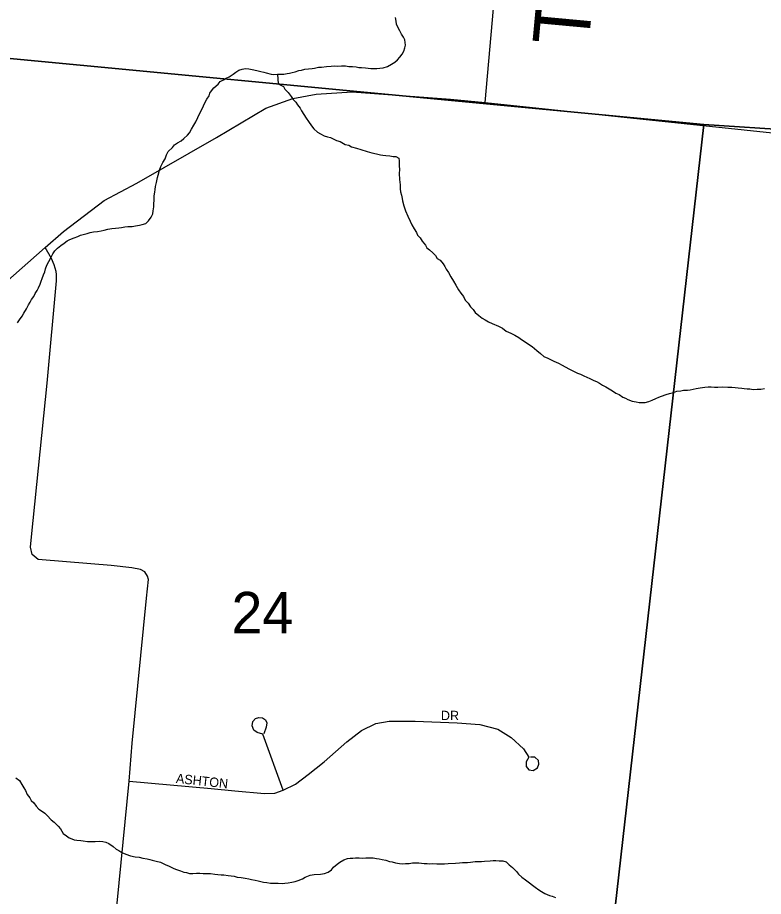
# Model space of a CAD drawing. Extents: x 0 to 1064, y 0 to 440.
# Drawn here: x 282.84 to 294.9, y 236.99 to 251.21 of the extents above; entities that cross this region are included whole.
import ezdxf

# ---------------------------------------------------------------- set-up
doc = ezdxf.new("R2010")
doc.units = 0
for name, color, linetype in [('GM_X_County_Road', 7, 'Continuous'), ('GM_X_Minor_River', 7, 'Continuous'), ('GM_X_Section', 7, 'Continuous'), ('GM_X_Section_Text', 7, 'Continuous'), ('GM_X_Township_Road', 7, 'Continuous'), ('GM_X_Township_Road_Text', 7, 'Continuous'), ('GM_X_Township_Subdivision', 7, 'Continuous'), ('GM_X_Township_Subdivision_Text', 7, 'Continuous')]:
    doc.layers.add(name, color=color, linetype=linetype)

msp = doc.modelspace()

# ---------------------------------------------------------------- linework, layer by layer
at = {"layer": 'GM_X_County_Road'}
msp.add_lwpolyline([(282.12, 246.458), (283.289, 247.487), (283.585, 247.745), (284.245, 248.251), (284.769, 248.528), (286.06, 249.268), (286.855, 249.742), (287.293, 249.898), (287.673, 249.968), (288.256, 250.004), (289.845, 249.886), (290.404, 249.835), (296.737, 249.166)], dxfattribs=at)
at = {"layer": 'GM_X_Minor_River'}
for points in [[(287.39, 250.352), (287.433, 250.357), (287.488, 250.374), (287.549, 250.378), (287.604, 250.382), (287.647, 250.387), (287.708, 250.403), (287.757, 250.408), (287.837, 250.417), (287.916, 250.421), (287.971, 250.425), (288.019, 250.424), (288.081, 250.428), (288.147, 250.426), (288.202, 250.418), (288.257, 250.417), (288.317, 250.409), (288.36, 250.401), (288.402, 250.4), (288.469, 250.392), (288.512, 250.391), (288.554, 250.383), (288.603, 250.382), (288.651, 250.386), (288.7, 250.391), (288.755, 250.395), (288.823, 250.417), (288.891, 250.452), (288.941, 250.487), (288.985, 250.522), (289.023, 250.569), (289.061, 250.617), (289.087, 250.664), (289.107, 250.718), (289.114, 250.761), (289.11, 250.803), (289.105, 250.846), (289.082, 250.889), (289.053, 250.939), (289.025, 250.994), (288.99, 251.05), (288.973, 251.099), (288.963, 251.148), (288.953, 251.209)], [(283.263, 247.048), (283.283, 247.096), (283.296, 247.144), (283.317, 247.205), (283.349, 247.264), (283.382, 247.324), (283.414, 247.384), (283.446, 247.437), (283.49, 247.479), (283.54, 247.52), (283.596, 247.56), (283.646, 247.595), (283.69, 247.618), (283.757, 247.646), (283.819, 247.669), (283.862, 247.686), (283.905, 247.697), (283.967, 247.713), (284.016, 247.73), (284.071, 247.74), (284.138, 247.75), (284.193, 247.761), (284.243, 247.771), (284.304, 247.787), (284.365, 247.798), (284.426, 247.802), (284.481, 247.806), (284.524, 247.811), (284.579, 247.822), (284.628, 247.826), (284.695, 247.83), (284.75, 247.841), (284.817, 247.851), (284.86, 247.861), (284.916, 247.878), (284.96, 247.919), (285.004, 247.978), (285.03, 248.032), (285.038, 248.081), (285.046, 248.147), (285.048, 248.202), (285.05, 248.25), (285.052, 248.323), (285.06, 248.384), (285.068, 248.426), (285.075, 248.474), (285.09, 248.541), (285.105, 248.619), (285.118, 248.661), (285.139, 248.739), (285.159, 248.8), (285.192, 248.865), (285.23, 248.925), (285.251, 248.985), (285.277, 249.039), (285.346, 249.104), (285.378, 249.151), (285.427, 249.18), (285.489, 249.215), (285.533, 249.25), (285.59, 249.303), (285.622, 249.344), (285.654, 249.404), (285.693, 249.469), (285.725, 249.523), (285.757, 249.589), (285.797, 249.673), (285.829, 249.732), (285.849, 249.78), (285.869, 249.828), (285.901, 249.888), (285.94, 249.942), (285.953, 249.984), (285.979, 250.025), (286.017, 250.073), (286.086, 250.131), (286.118, 250.173), (286.173, 250.202), (286.217, 250.225), (286.266, 250.247), (286.329, 250.294), (286.372, 250.323), (286.422, 250.358), (286.477, 250.374), (286.526, 250.385), (286.581, 250.377), (286.636, 250.37), (286.714, 250.349), (286.774, 250.335), (286.823, 250.327), (286.865, 250.314), (286.944, 250.293), (286.986, 250.286), (287.047, 250.29), (287.108, 250.294), (287.151, 250.293), (287.2, 250.304), (287.242, 250.308), (287.285, 250.319), (287.334, 250.33), (287.39, 250.352)], [(287.047, 250.29), (287.059, 250.138), (287.144, 250.093), (287.167, 250.049), (287.22, 249.993), (287.267, 249.931), (287.301, 249.881), (287.343, 249.838), (287.372, 249.794), (287.413, 249.744), (287.436, 249.701), (287.47, 249.639), (287.511, 249.583), (287.546, 249.528), (287.598, 249.459), (287.633, 249.41), (287.692, 249.353), (287.74, 249.327), (287.8, 249.295), (287.854, 249.281), (287.902, 249.268), (287.944, 249.248), (287.998, 249.222), (288.058, 249.202), (288.142, 249.157), (288.197, 249.143), (288.244, 249.117), (288.323, 249.097), (288.395, 249.076), (288.498, 249.043), (288.57, 249.022), (288.649, 249.002), (288.709, 248.988), (288.751, 248.98), (288.8, 248.979), (288.861, 248.971), (288.915, 248.963), (288.958, 248.962), (289.006, 248.936), (289.016, 248.893), (289.015, 248.851), (289.014, 248.808), (289.018, 248.753), (289.016, 248.687), (289.019, 248.589), (289.028, 248.504), (289.032, 248.437), (289.036, 248.389), (289.053, 248.333), (289.063, 248.284), (289.068, 248.242), (289.09, 248.162), (289.118, 248.082), (289.151, 247.996), (289.191, 247.916), (289.22, 247.854), (289.254, 247.793), (289.295, 247.731), (289.312, 247.688), (289.353, 247.644), (289.388, 247.594), (289.44, 247.526), (289.463, 247.483), (289.505, 247.451), (289.558, 247.401), (289.599, 247.357), (289.628, 247.313), (289.676, 247.282), (289.723, 247.226), (289.752, 247.182), (289.775, 247.139), (289.809, 247.083), (289.85, 247.015), (289.89, 246.947), (289.931, 246.879), (289.971, 246.805), (290.012, 246.749), (290.053, 246.699), (290.081, 246.638), (290.128, 246.587), (290.169, 246.532), (290.21, 246.488), (290.245, 246.438), (290.304, 246.388), (290.357, 246.344), (290.405, 246.318), (290.459, 246.286), (290.519, 246.26), (290.621, 246.214), (290.687, 246.182), (290.746, 246.137), (290.818, 246.105), (290.884, 246.072), (290.95, 246.034), (290.992, 246.002), (291.051, 245.964), (291.105, 245.926), (291.164, 245.887), (291.242, 245.824), (291.301, 245.774), (291.354, 245.724)], [(282.842, 246.272), (282.874, 246.319), (282.918, 246.379), (282.944, 246.427), (282.989, 246.498), (283.022, 246.564), (283.047, 246.606), (283.067, 246.647), (283.105, 246.695), (283.125, 246.743), (283.157, 246.796), (283.183, 246.838), (283.209, 246.898), (283.223, 246.946), (283.243, 246.988), (283.263, 247.048)], [(291.354, 245.724), (291.42, 245.697), (291.462, 245.678), (291.516, 245.652), (291.588, 245.619), (291.648, 245.587), (291.755, 245.529), (291.833, 245.49), (291.899, 245.458), (291.947, 245.438), (292.001, 245.412), (292.049, 245.392), (292.097, 245.373), (292.163, 245.34), (292.205, 245.321), (292.253, 245.295), (292.301, 245.263), (292.355, 245.237), (292.409, 245.205), (292.462, 245.173), (292.516, 245.135), (292.57, 245.109), (292.629, 245.071), (292.671, 245.051), (292.713, 245.032), (292.779, 245.006), (292.846, 244.991), (292.894, 244.984), (292.949, 244.982), (292.992, 244.981), (293.053, 244.997), (293.103, 245.02), (293.165, 245.048), (293.214, 245.071), (293.257, 245.082), (293.331, 245.11), (293.386, 245.126), (293.448, 245.143), (293.503, 245.165), (293.57, 245.169), (293.613, 245.18), (293.674, 245.184), (293.717, 245.189), (293.766, 245.2), (293.815, 245.21), (293.883, 245.22), (293.956, 245.23), (294.011, 245.235), (294.06, 245.233), (294.114, 245.232), (294.169, 245.23), (294.242, 245.234), (294.327, 245.231), (294.394, 245.229), (294.449, 245.227), (294.497, 245.22), (294.552, 245.212), (294.595, 245.211), (294.643, 245.203), (294.686, 245.202), (294.74, 245.194), (294.801, 245.198), (294.862, 245.196), (294.923, 245.207)], [(282.813, 238.912), (282.872, 238.867), (282.913, 238.805), (282.942, 238.75), (282.971, 238.706), (282.999, 238.645), (283.04, 238.589), (283.063, 238.546), (283.104, 238.508), (283.145, 238.452), (283.186, 238.408), (283.228, 238.376), (283.281, 238.338), (283.323, 238.301), (283.387, 238.232), (283.435, 238.194), (283.5, 238.131), (283.535, 238.088), (283.581, 238.013), (283.635, 237.975), (283.676, 237.944), (283.718, 237.924), (283.76, 237.911), (283.803, 237.903), (283.864, 237.901), (283.906, 237.894), (283.973, 237.88), (284.058, 237.883)], [(284.058, 237.883), (284.1, 237.882), (284.161, 237.886), (284.222, 237.884), (284.271, 237.871), (284.319, 237.851), (284.39, 237.8), (284.437, 237.756), (284.479, 237.737), (284.527, 237.705), (284.593, 237.678), (284.671, 237.652), (284.744, 237.637), (284.811, 237.629), (284.871, 237.615), (284.938, 237.601), (284.98, 237.594), (285.022, 237.58), (285.083, 237.566), (285.155, 237.546), (285.239, 237.507), (285.281, 237.487), (285.371, 237.448), (285.413, 237.428), (285.479, 237.408), (285.533, 237.388), (285.576, 237.381), (285.624, 237.367), (285.679, 237.365), (285.734, 237.37), (285.788, 237.368), (285.843, 237.366), (285.898, 237.365), (285.965, 237.363), (286.032, 237.355), (286.08, 237.347), (286.135, 237.345), (286.177, 237.344), (286.25, 237.33), (286.299, 237.328), (286.347, 237.32), (286.395, 237.307), (286.456, 237.299), (286.523, 237.291), (286.583, 237.277), (286.626, 237.269), (286.686, 237.255), (286.734, 237.248), (286.777, 237.234), (286.819, 237.227), (286.874, 237.219), (286.934, 237.211), (286.989, 237.21), (287.056, 237.207), (287.123, 237.205), (287.165, 237.21), (287.22, 237.215), (287.276, 237.225), (287.331, 237.235), (287.38, 237.252), (287.448, 237.28), (287.491, 237.303), (287.572, 237.337), (287.639, 237.347), (287.743, 237.356), (287.804, 237.367), (287.865, 237.389), (287.921, 237.424), (287.953, 237.465), (288.01, 237.518), (288.053, 237.547), (288.116, 237.588), (288.177, 237.61), (288.22, 237.615), (288.263, 237.614), (288.305, 237.618), (288.366, 237.616), (288.427, 237.615), (288.476, 237.619), (288.543, 237.617), (288.591, 237.616), (288.646, 237.608), (288.688, 237.6), (288.737, 237.593), (288.797, 237.579), (288.857, 237.559), (288.9, 237.551), (288.954, 237.538), (289.021, 237.529), (289.063, 237.522), (289.118, 237.526), (289.173, 237.525), (289.228, 237.535), (289.283, 237.54), (289.332, 237.538), (289.417, 237.529), (289.465, 237.528), (289.508, 237.52), (289.557, 237.525), (289.623, 237.523), (289.696, 237.521)], [(289.696, 237.521), (289.745, 237.519), (289.806, 237.529), (289.922, 237.532), (289.989, 237.536), (290.038, 237.541), (290.117, 237.544), (290.166, 237.549), (290.24, 237.559), (290.294, 237.557), (290.343, 237.561), (290.392, 237.566), (290.484, 237.569), (290.532, 237.574), (290.575, 237.573), (290.63, 237.571), (290.691, 237.569), (290.745, 237.555), (290.792, 237.505), (290.845, 237.461), (290.91, 237.398), (290.945, 237.355), (290.998, 237.304), (291.058, 237.26), (291.123, 237.215), (291.171, 237.178), (291.212, 237.146), (291.272, 237.102), (291.314, 237.076), (291.367, 237.044), (291.445, 237.011), (291.488, 236.998), (291.542, 236.978)]]:
    msp.add_lwpolyline(points, dxfattribs=at)
at = {"layer": 'GM_X_Section'}
for points in [[(297.266, 269.783), (295.423, 249.38), (293.94, 249.48), (278.753, 250.922), (280.582, 271.247)], [(277.718, 251.02), (278.753, 250.922), (293.94, 249.48), (292.003, 232.393), (276.183, 234.07)], [(295.423, 249.38), (309.214, 248.091), (307.602, 230.968), (292.003, 232.393), (293.94, 249.48)]]:
    msp.add_lwpolyline(points, close=True, dxfattribs=at)
at = {"layer": 'GM_X_Township_Road'}
for points in [[(290.404, 249.835), (290.697, 253.124), (290.743, 253.401), (290.806, 253.714), (290.932, 254.003), (290.959, 254.185), (291.075, 257.42), (291.093, 257.615), (291.149, 257.715), (291.21, 257.775), (291.343, 257.808), (291.564, 257.81), (291.632, 257.852), (291.662, 257.911), (291.683, 257.979), (291.956, 260.238), (292.789, 270.143), (293.054, 270.127), (293.155, 270.125)], [(284.423, 236.557), (284.648, 238.859), (284.698, 239.473), (284.929, 241.82), (284.959, 242.12), (284.944, 242.172), (284.9, 242.242), (284.833, 242.282), (284.693, 242.307), (284.356, 242.344), (283.636, 242.408), (283.176, 242.445), (283.08, 242.525), (283.053, 242.644), (283.068, 242.809), (283.323, 245.294), (283.475, 246.949), (283.471, 247.05), (283.466, 247.103), (283.435, 247.208), (283.39, 247.311), (283.289, 247.487)]]:
    msp.add_lwpolyline(points, dxfattribs=at)
at = {"layer": 'GM_X_Township_Subdivision'}
for points in [[(284.648, 238.859), (285.976, 238.737), (286.358, 238.7), (286.837, 238.658), (287.004, 238.666), (287.139, 238.713), (287.339, 238.809), (287.543, 238.966), (287.801, 239.173), (288.167, 239.494), (288.404, 239.678), (288.637, 239.789), (288.85, 239.826), (289.27, 239.826), (289.951, 239.801), (290.317, 239.774), (290.607, 239.697), (290.827, 239.565), (291.024, 239.381), (291.11, 239.248), (291.069, 239.172), (291.066, 239.097), (291.112, 239.039), (291.183, 239.033), (291.25, 239.076), (291.274, 239.132), (291.266, 239.19), (291.205, 239.249), (291.138, 239.249)], [(287.139, 238.713), (286.811, 239.62), (286.718, 239.647), (286.661, 239.684), (286.639, 239.753), (286.647, 239.821), (286.692, 239.871), (286.745, 239.89), (286.801, 239.881), (286.851, 239.849), (286.871, 239.801), (286.863, 239.733), (286.826, 239.626)]]:
    msp.add_lwpolyline(points, dxfattribs=at)

# ---------------------------------------------------------------- texts
at = {"layer": 'GM_X_Section_Text'}
msp.add_text('24', height=0.6697, rotation=0, dxfattribs=at).set_placement((286.303, 241.249))
at = {"layer": 'GM_X_Township_Road_Text'}
msp.add_text('T-95', height=0.9091, rotation=84.7102, dxfattribs=at).set_placement((292.074, 250.724))
at = {"layer": 'GM_X_Township_Subdivision_Text'}
for s, rotation, p in [('DR', 0, (289.689, 239.845)), ('ASHTON', 353.8839, (285.399, 238.831))]:
    msp.add_text(s, height=0.1515, rotation=rotation, dxfattribs=at).set_placement(p)

doc.saveas('drawing.dxf')
